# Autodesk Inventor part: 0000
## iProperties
Shininess: 64.0
Length Units: 11269
Angle Units: 11279
Time Units: 11290
Mass Units: 11283
Length Display Precision: 3
Angle Display Precision: 2
Compacted: True
Part Number: 0000
Document SubType Name: Sheet Metal
Created: 2004-02
Material: Par défaut
Project: GB000
Manufacturer: Standard
Standards Organization: Custom
Density: 0.0
Volumn: 0.0
Area: 0.0
PropertySet Name: Model Information
Control State: 0
Master: False
Checked Out: False
Observations: -
Revision Number: 00
